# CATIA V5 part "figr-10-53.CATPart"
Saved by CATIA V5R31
Part number: Part1
Bounding box of the stored display mesh (mm): x 0 to 100, y -43.492 to 31.468, z -3.623 to 11.497
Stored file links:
  D:\PROJECTS\Project 2021\US EDITION\CATIA V5 6R 2021\Resources\Part Files\c10_catia_v5_6r2021_prt\c10_catia_v5_6r2021_prt\figr-10-53.CATPart
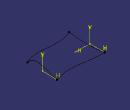
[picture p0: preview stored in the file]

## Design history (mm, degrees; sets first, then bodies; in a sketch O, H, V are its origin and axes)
Set1
  Sketch1 on yz-plane, origin (0, 0, 0), H (0, 1, 0), V (0, 0, 1)
  Plane1: type Offset, RefPlane yz-plane, Offset 100
  Sketch2 on xy-plane, origin (0, 0, 0), H (1, 0, 0), V (0, 1, 0)
    spline S1 through (0, 31.0443) (19.7053, 31.0443) (51.809, 26.4574) (100, 31.0443)
    reference intersected line E1 through (100, 0) direction (0, 1) from Plane1
    point P1 (0, 31.0443)
    point P2 (100, 31.0443)
    coincidence: P1 V, P2 E1
  Sketch3 on xy-plane, origin (0, 0, 0), H (1, 0, 0), V (0, 1, 0)
    spline S1 through (0, -43.492) (26.209, -36.2295) (80.3728, -38.1407) (100, -32.0249)
    reference intersected line E1 through (100, 0) direction (0, 1) from Plane1
    point P1 (0, -43.492)
    point P2 (100, -32.0249)
    coincidence: P1 V, P2 E1
  Sketch4 on Plane1, origin (100, 0, 0), H (0, 1, 0), V (0, 0, 1)
    spline S1 through (-32.0249, 0) (-14.5305, 11.3827) (11.9668, 5.3652) (31.0443, 0)
    reference projected point E1 (31.0443, 0) from vertex of Sketch2
    reference projected point E2 (-32.0249, 0) from vertex of Sketch3
    point P1 (-32.0249, 0)
    point P2 (31.0443, 0)
    coincidence: P1 H, P2 H, P2 E1, P1 E2
  Sketch5 on yz-plane, origin (0, 0, 0), H (0, 1, 0), V (0, 0, 1)
    spline S1 through (31.0443, 0) (7.4727, -3.1675) (-43.492, 0)
    reference projected point E1 (-43.492, 0) from vertex of Sketch3
    reference projected point E2 (31.0443, 0) from vertex of Sketch2
    point P1 (31.0443, 0)
    point P2 (-43.492, 0)
    coincidence: P1 H, P2 H, P2 E1, P1 E2
Body1 (main body)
